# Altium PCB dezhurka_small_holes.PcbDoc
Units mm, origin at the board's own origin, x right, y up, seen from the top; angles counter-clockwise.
Board outline 60 x 25.5 mm, 2 copper layers (Top Layer, Bottom Layer); 30 components, 21 nets, 83 pads, 0 vias.
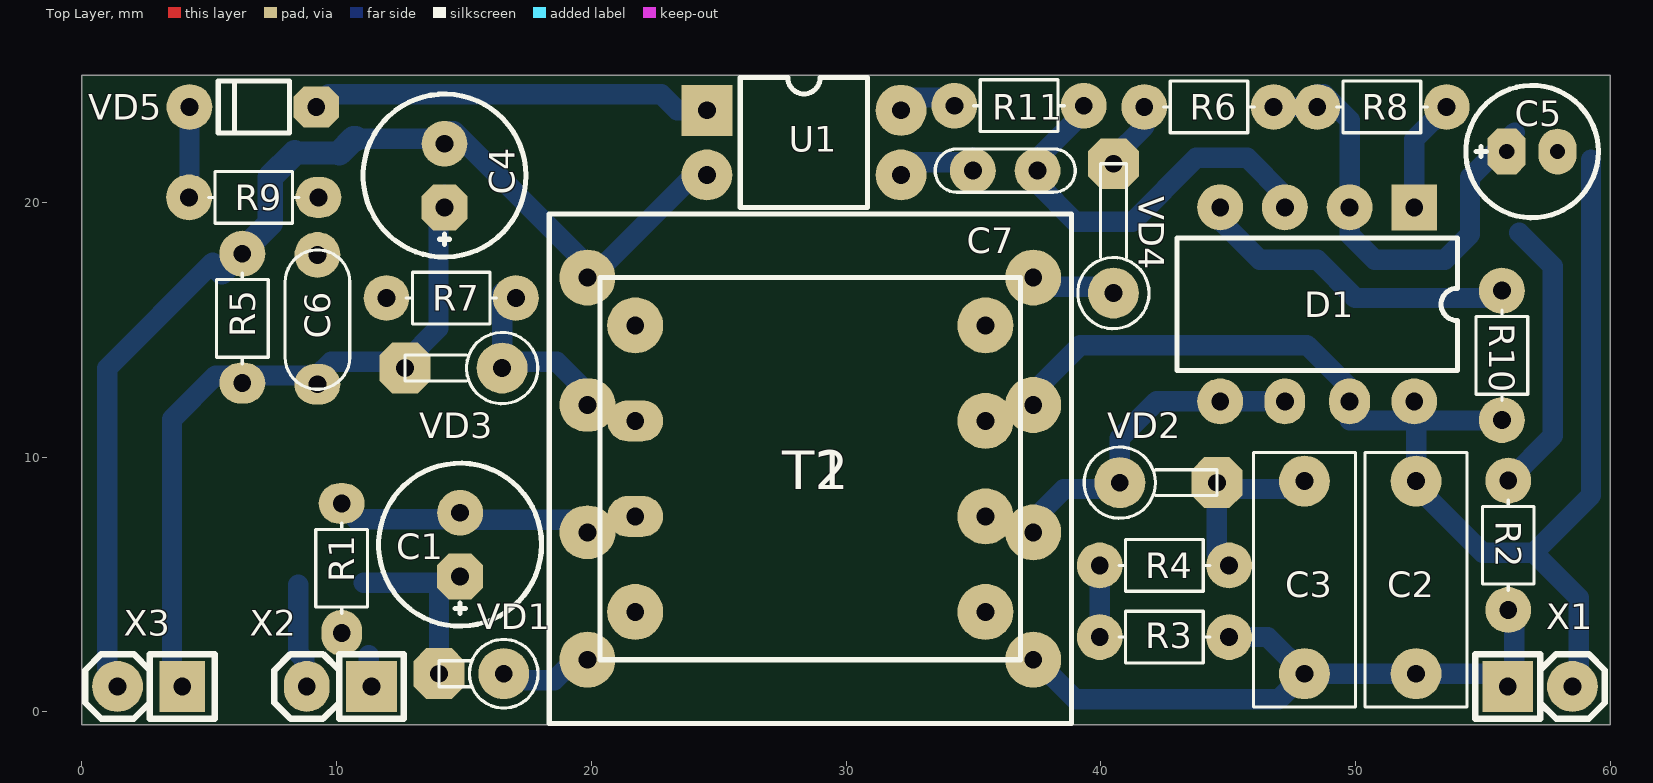
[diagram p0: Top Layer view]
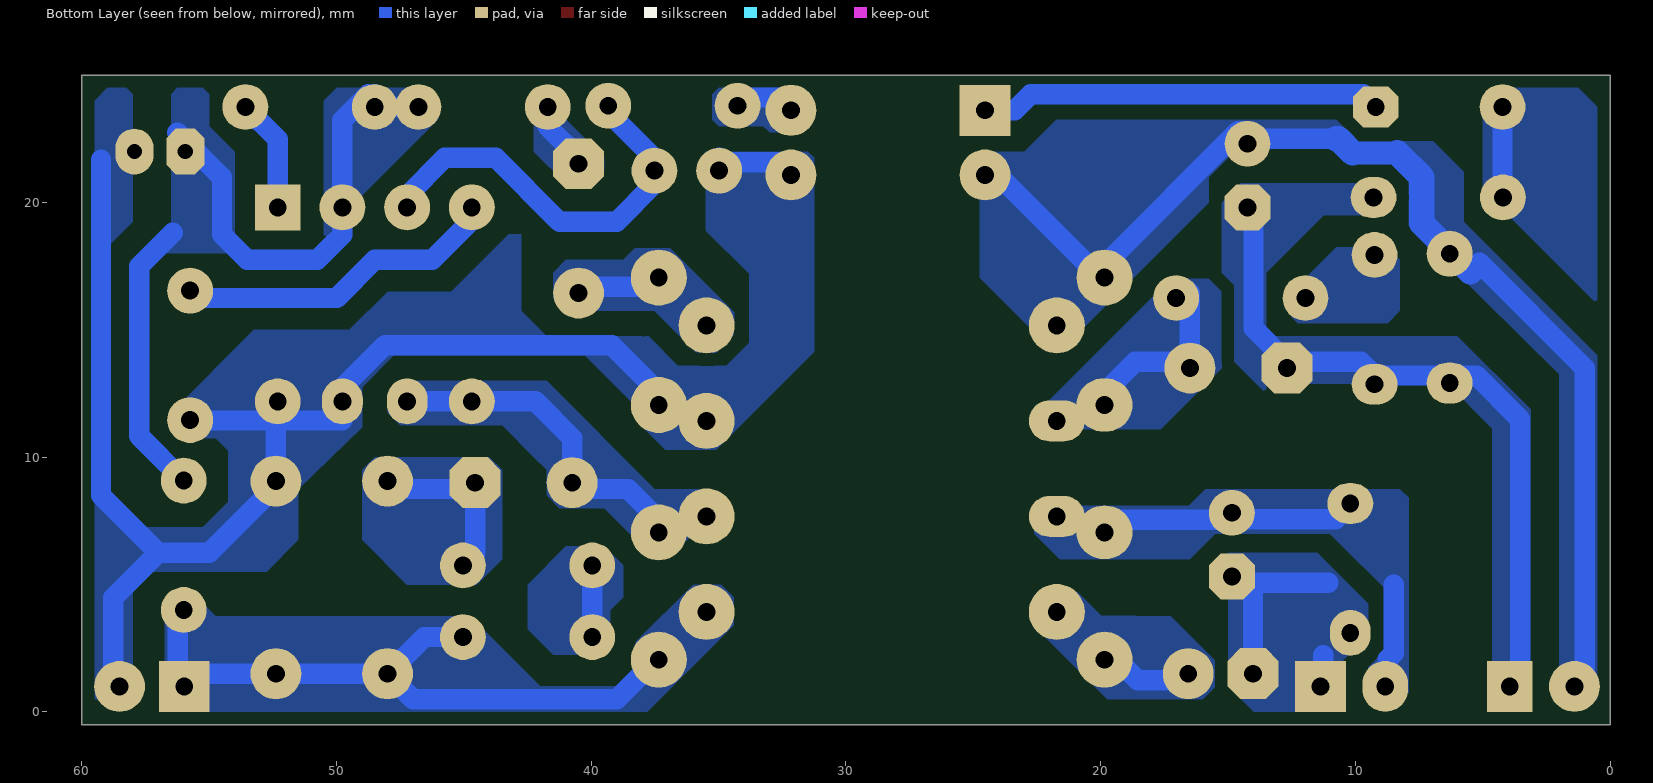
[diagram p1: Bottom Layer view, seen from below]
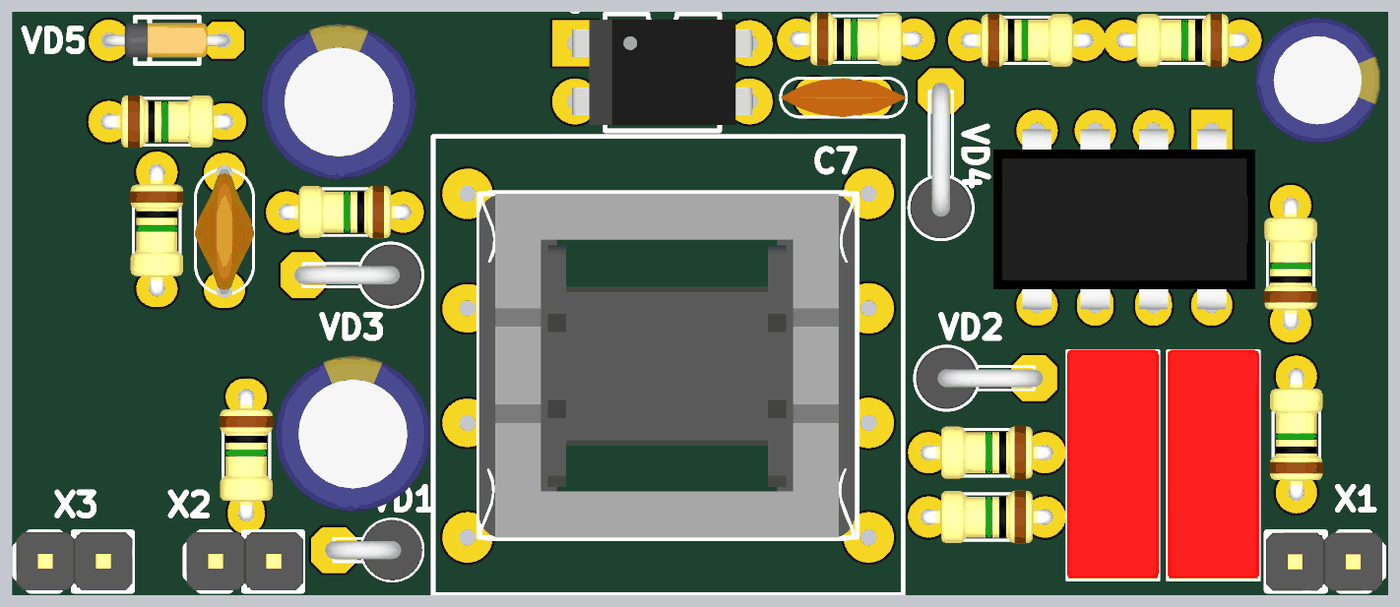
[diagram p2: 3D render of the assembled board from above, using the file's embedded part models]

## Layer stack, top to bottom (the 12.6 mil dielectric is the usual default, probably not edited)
Top Solder: solder mask 0.0102, Solder Resist, Dk 3.5
Top Layer: signal copper 0.0356
Dielectric 1: dielectric 0.32, FR-4, Dk 4.8
Bottom Layer: signal copper 0.0356
Bottom Solder: solder mask 0.0102, Solder Resist, Dk 3.5

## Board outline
0,-0.5 0,25 60,25 60,-0.5

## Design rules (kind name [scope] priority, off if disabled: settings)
Clearance [All] p1: gap=0.5 ignorepadtopadclearanceinfootprint=FALSE
PolygonConnect [All] p1: connectstyle=Direct reliefconductorwidth=0.254 reliefentries=4 polygonreliefangle="90 Angle" airgapwidth=0.254
RoomDefinition dezhurka [InComponentClass('dezhurka')] p1: confinementstyle=ConfineIn formatcopy=TRUE lockcomponents=FALSE outline 0,-0.5 60.2,-0.5 60.2,25 0,25
RoutingVias [All] p1: holewidth=0.711 width=1.27 viastyle="Through Hole" minholewidth=0.711 minwidth=1.27 maxholewidth=0.711 maxwidth=1.27
SolderMaskExpansion [All] p1: expansion=0.102
Width [All] p1: maxlimit=2 minlimit=0.3 preferedwidth=0.4
30 further rules are at their usual default settings.

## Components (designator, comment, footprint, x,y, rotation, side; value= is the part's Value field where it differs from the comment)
C1 "*" D6.3C2.5H11 14.85,6.567 r90 top
C2 "*" "MKP 10x4 h9 R7.62" 52.381,5.25 r90 top
C3 "*" "MKP 10x4 h9 R7.62" 48,5.25 r90 top
C4 "*" D6.3C2.5H11 14.237,21.057 r90 top
C5 "*" D5C2H11 56.936,22 r0 top
C6 "*" Cap-Disk-D5.5-R5.08 9.25,15.401 r270 top
C7 "*" Cap-Disk-D5.5-R2.54 36.25,21.25 r180 top
D1 "OB2358" 8-DIP 48.5,16 r270 top
R1 "*" R0.125-200#1 10.2,5.643 r270 top
R2 "*" R0.125-200#2 56,6.543 r90 top
R3 "*" R0.125-200#2 42.5,2.94 r180 top
R4 "*" R0.125-200#2 42.5,5.75 r180 top
R5 "*" R0.125-200#3 6.3,15.451 r270 top
R6 "*" R0.125-200#2 44.25,23.75 r0 top
R7 "*" R0.125-200#2 14.5,16.25 r180 top
R8 "*" R0.125-200#2 51.04,23.75 r180 top
R9 "*" R0.125-200#4 6.75,20.2 r0 top
R10 "*" R0.125-200#2 55.75,14 r90 top
R11 "*" R0.125-200#2 36.796,23.799 r0 top
T1 "3FD-312" "TRANS: EFD20_8Pin" 28.6,9.55 r90 top
T2 "3FD-312" "TRANS: EFD15_8Pin" 28.6,9.55 r90 top (schematic designator T1)
U1 "LTV-817S" 4-DIP 28.35,22.35 r0 top
VD1 "*" "DO-41 Ver-100" 16.563,1.5 r180 top
VD2 "*" "DO-41 Ver-150" 40.75,9 r0 top
VD3 "*" "DO-41 Ver-150" 16.5,13.5 r180 top
VD4 "*" "DO-41 Ver-200R" 40.5,16.443 r90 top
VD5 "*" DO35 6.75,23.75 r180 top
X1 "*" "CON: PLS-2"#1 57.25,1 r0 top
X2 "*" "CON: PLS-2"#2 10.1,1 r180 top
X3 "*" "CON: PLS-2"#3 2.67,1 r180 top

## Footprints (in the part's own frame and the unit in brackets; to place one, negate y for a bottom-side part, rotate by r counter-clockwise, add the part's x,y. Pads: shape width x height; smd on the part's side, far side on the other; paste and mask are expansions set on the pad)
4-DIP [mm]
  round 0.7 on Mech1: 0(-3.3,1.7)
  rect 2x2 hole 0.7: 1(-3.81,1.27)
  round 2 hole 0.7: 2(-3.81,-1.27) 3(3.81,-1.27) 4(3.81,1.27)
  round 0.7 on Top Overlay: 2(-3.8,2.9)
  silkscreen extent -2.5,-2.55 2.5,2.55, body extent -3.94,-2.3 3.94,2.3, height 3.66
8-DIP [mm]
  rect 1.8x1.8 hole 0.7: 1(-3.81,3.81)
  round 1.8 hole 0.7: 2(-3.81,1.27) 3(-3.81,-1.27) 4(-3.81,-3.81) 5(3.81,-3.81) 8(3.81,3.81)
  oval 1.8x1.6 hole 0.7: 6(3.81,-1.27) 7(3.81,1.27)
  round 0.5 on Mech1: ""(-3.3,5.1)
  silkscreen extent -2.6,-5.5 2.6,5.5, body extent -3.87,-5.71 4,5.71, height 4.19
Cap-Disk-D5.5-R2.54 [mm]
  round 1.8 hole 0.7: 1(-1.27,0) 2(1.27,0)
  silkscreen extent -2.75,-0.85 2.75,0.85, body extent -2.74,-0.86 2.75,0.86, height 6.25
Cap-Disk-D5.5-R5.08 [mm]
  round 1.8 hole 0.7: 1(-2.54,0)
  oval 1.6x1.8 hole 0.7: 2(2.54,0)
  silkscreen extent -2.73,-1.27 2.73,1.27, body extent -2.73,-1.27 2.73,1.27, height 7.62
"CON: PLS-2"#1 [mm]
  rect 2x2 hole 0.7: 1(-1.27,0)
  round 2 hole 0.7: 2(1.27,0)
  silkscreen extent -2.54,-1.27 2.54,1.27, body extent -2.57,-1.28 2.51,1.26, height 8.54
"CON: PLS-2"#2 [mm]
  rect 2x2 hole 0.7: 1(-1.27,0)
  oval 1.8x2 hole 0.7: 2(1.27,0)
  silkscreen extent -2.54,-1.27 2.54,1.27, body extent -2.57,-1.28 2.51,1.26, height 8.54
"CON: PLS-2"#3 [mm]
  rect 1.8x2 hole 0.7: 1(-1.27,0)
  round 2 hole 0.7: 2(1.27,0)
  silkscreen extent -2.54,-1.27 2.54,1.27, body extent -2.57,-1.28 2.51,1.26, height 8.54
D5C2H11 [mm] "Polar capacitor, diameter 5 mm, leads clearance 2 mm, height 11 mm"
  oct 1.5x1.8 hole 0.6: 1(-1,0)
  oval 1.5x1.8 hole 0.6: 2(1,0)
  silkscreen extent -2.6,-2.6 2.6,2.6, body extent -2.75,-2.75 2.75,2.75, height 13.5
D6.3C2.5H11 [mm] "Polar capacitor, diameter 6.3 mm, leads clearance 2.5 mm, height 11 mm"
  oct 1.8x1.8 hole 0.7: 1(-1.25,0)
  round 1.8 hole 0.7: 2(1.25,0)
  silkscreen extent -3.2,-3.2 3.2,3.2, body extent -3.4,-3.4 3.4,3.4, height 12.5
DO35 [mm]
  oct 1.8x1.6 hole 0.7: 1(-2.45,0)
  round 1.8 hole 0.7: 2(2.525,0)
  silkscreen extent -1.4,-1.02 1.4,1.02, body extent -2.7,-0.75 2.8,0.75, height 2.75
"DO-41 Ver-100" [mm]
  round 2 hole 0.7: 1(0,0)
  oct 2x2 hole 0.7: 2(2.54,0)
  silkscreen extent -1.35,-1.35 2.54,1.35, body extent -1.33,-1.33 2.93,1.33, height 6.84
"DO-41 Ver-150" [mm]
  round 2 hole 0.7: 1(0,0)
  oct 2x2 hole 0.7: 2(3.81,0)
  silkscreen extent -1.4,-1.4 3.81,1.4, body extent -1.33,-1.33 4.2,1.33, height 6.84
"DO-41 Ver-200R" [mm]
  round 2 hole 0.7: 1(0,0)
  oct 2x2 hole 0.7: 2(5.08,0)
  silkscreen extent -1.4,-1.4 5.08,1.4, body extent -1.33,-1.33 5.82,1.55, height 6.84
"MKP 10x4 h9 R7.62" [mm]
  round 2 hole 0.7: 1(-3.75,0) 2(3.81,0)
  silkscreen extent -5.06,-2 4.94,2, body extent -5,-2 5,2, height 9
R0.125-200#1 [mm]
  oval 1.6x1.8 hole 0.7: 1(-2.54,0)
  oval 1.8x1.6 hole 0.7: 2(2.54,0)
  silkscreen extent -1.78,-1.02 1.78,1.02, body extent -2.84,-1.15 2.84,1.15, height 2.93
R0.125-200#2 [mm]
  round 1.8 hole 0.7: 1(-2.54,0) 2(2.54,0)
  silkscreen extent -1.78,-1.02 1.78,1.02, body extent -2.84,-1.15 2.84,1.15, height 2.93
R0.125-200#3 [mm]
  round 1.8 hole 0.7: 1(-2.54,0)
  oval 1.6x1.8 hole 0.7: 2(2.54,0)
  silkscreen extent -1.78,-1.02 1.78,1.02, body extent -2.84,-1.15 2.84,1.15, height 2.93
R0.125-200#4 [mm]
  round 1.8 hole 0.7: 1(-2.54,0)
  oval 1.8x1.6 hole 0.7: 2(2.54,0)
  silkscreen extent -1.78,-1.02 1.78,1.02, body extent -2.84,-1.15 2.84,1.15, height 2.93
"TRANS: EFD15_8Pin" [mm]
  round 2.2 hole 0.7: 1(-5.625,-6.875) 2(-1.875,-6.875) 3(1.875,-6.875) 4(5.625,-6.875) 5(-5.625,6.875) 8(5.625,6.875)
  oval 1.6x2.2 hole 0.7: 6(-1.875,6.875) 7(1.875,6.875)
  silkscreen extent -7.5,-8.25 7.5,8.25, body extent -7.65,-8.18 7.65,8.25, height 8.41
"TRANS: EFD20_8Pin" [mm]
  round 2.2 hole 0.7: 1(-7.5,-8.75) 2(-2.5,-8.75) 3(2.5,-8.75) 4(7.5,-8.75) 5(-7.5,8.75) 8(7.5,8.75)
  oval 2.1x2.2 hole 0.7: 6(-2.5,8.75) 7(2.5,8.75)
  silkscreen extent -10,-10.25 10,10.25

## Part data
C1 C4 C5: library part AlumCap
C2 C3 C6 C7: library part Capacitor
D1: "Sensor", Manufacturer="Texas Instruments"
R1 R2 R3 R4 R5 R6 R7 R8 R9 R10 R11: library part Resistor
T1 T2: library part EFD20_2_OUTPUT, "Sensor", Manufacturer=Tamura
U1: library part Optoisolator, Manufacturer="Lite-On Inc."
VD1 VD2 VD3 VD4: library part Diod
VD5: library part "Diod Zener"
X1 X2 X3: library part 2-Connector

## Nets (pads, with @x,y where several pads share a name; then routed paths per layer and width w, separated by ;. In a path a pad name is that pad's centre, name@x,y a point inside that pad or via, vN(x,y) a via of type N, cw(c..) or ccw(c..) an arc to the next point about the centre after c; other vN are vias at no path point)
NetC1_1: C1.1 R1.2 VD1.2 X2.1 | length 8.7
  Bottom Layer w0.8: 11.064,5.067 14.5,5.067 14.023,4.59 VD1.2 VD1.2@14.023,1.25 ; X2.1@11.27,1 11.27,2.233
NetC1_2: C1.2 R1.1 T1.6 T2.6 X2.2 | length 13.2
  Bottom Layer w0.8: 8.5,5 8.5,3.907 8.5,2.299 8.73,2.069 X2.2@8.73,1 ; R1.1@10.766,7.567 14.5,7.567 14.517,7.55 T1.6@19.85,7.55
NetC2_1: C2.1 C3.1 R2.1 R3.1 T1.1 T2.1 X1.1 | length 27.2
  Bottom Layer w0.8: T1.1@37.35,2.55 37.35,2.15 39,0.5 47,0.5 C3.1 ; R3.1 46.56,2.94 C3.1 ; R2.1 56.23,3.773 56.23,1 55.73,1.5 C2.1 C3.1
NetC2_2: C2.2 C5.2 C7.2 D1.7 D1.8 R10.1 T1.3 T2.3 U1.3 X1.2 | length 55.4
  Bottom Layer w0.8: U1.3@32.16,21.58 34.81,21.58 34.98,21.75 C7.2 ; T1.3@37.35,12.55 39.2,14.4 48.1,14.4 49.77,12.73 D1.7 49.77,11.44 D1.8@52.31,11.44 ; R10.1 55.73,11.44 D1.8@52.31,11.44 ; X1.2@58.77,1 58.77,4.48 57,6.25 ; 59.25,21.686 59.25,8.5 57,6.25 ; D1.8@52.31,11.44 52.381,11.369 C2.2 52.381,8.56 52.69,8.56 55,6.25 57,6.25
NetC3_2: C3.2 R4.1 VD2.2 | length 6.7
  Bottom Layer w0.8: R4.1 44.56,6.23 44.56,8.75 47.81,8.75 C3.2@48,8.56
NetC4_1: C4.1 C6.2 R5.2 R9.2 VD3.2 X3.1 | length 27.8
  Bottom Layer w0.8: X3.1@3.54,1 3.54,11.5 5.25,13.21 9.25,13.21 9.79,13.75 12.69,13.75 14,15.06 14,20.07 C4.1@14.237,20.307
NetC4_2: C4.2 R5.1 T1.8 T2.8 U1.2@24.54,21.08 X3.2 | length 44.8
  Bottom Layer w0.8: X3.2@1,1 1,13.5 5.145,17.645 ; 10.75,22.5 14.237,22.5 14.237,22.807 14.593,22.807 19.85,17.55 20.51,17.55 U1.2@24.54,21.58
  Bottom Layer w0.9: 8.35,21.95 10.114,21.95
  Bottom Layer w1: 5.5,17.29 7.39,19.18 7.39,20.99 8.35,21.95 ; 10.114,21.95 10.664,22.5 10.75,22.5
NetC5_1: C5.1 D1.2 R2.2 R6.2 R8.2 | length 29.2
  Bottom Layer w0.8: R6.2@46.54,23.75 R6.2 R8.2 ; R8.2@48.75,24.25 49.77,23.23 D1.2 49.77,18.73 50.75,17.75 53.5,17.75 54.5,18.75 54.5,21 C5.1@56.25,22.75 ; R2.2 57.75,10.833 57.75,17.5 56.436,18.814
NetC6_1: C6.1 R7.2
NetC7_1: C7.1 D1.3 R11.2 | length 15.6
  Bottom Layer w0.8: C7.1@37.5,20.75 39,19.25 41.25,19.25 43.75,21.75 45.75,21.75 47.23,20.27 D1.3 ; C7.1@37.52,21.5 37.52,21.733 R11.2@39.586,23.799
NetD1_1: D1.1 R8.1 | length 4.6
  Bottom Layer w0.8: D1.1 52.31,22.48 R8.1 R8.1@53.75,23.75
NetD1_4: D1.4 R10.2 | length 12.9
  Bottom Layer w0.8: D1.4 44.69,19.31 46.25,17.75 48.5,17.75 50,16.25 55.46,16.25 R10.2
NetD1_5: D1.5 D1.6 T1.2 T2.2 VD2.1 | length 13
  Bottom Layer w0.8: T1.2@37.35,7.55 38.55,8.75 40.75,8.75 VD2.1 40.75,10.75 42.19,12.19 D1.5 D1.6
NetR3_2: R3.2 R4.2 | length 2.6
  Bottom Layer w0.8: R3.2@39.96,3.19 R4.2
NetR6_1: R6.1 VD4.2 | length 2.5
  Bottom Layer w0.8: VD4.2@40.5,21.773 41.71,22.983 R6.1
NetR7_1: R7.1 T1.7 T2.7 VD3.1 | length 6.6
  Bottom Layer w0.8: R7.1@16.5,16.46 16.5,13.75 18.65,13.75 T1.7@19.85,12.55
NetR9_1: R9.1 VD5.2 | length 3.3
  Bottom Layer w0.8: R9.1@4.21,20.5 4.225,20.515 VD5.2
NetR11_1: R11.1 U1.4 | length 1.9
  Bottom Layer w0.8: U1.4@32.41,24.12 R11.1@34.327,24.12
NetT1_4: T1.4 T2.4 VD4.1 | length 3.5
  Bottom Layer w0.8: T1.4@37.35,17.55 38.207,16.693 VD4.1@40.5,16.693
NetT1_5: T1.5 T2.5 VD1.1 | length 3.8
  Bottom Layer w0.8: VD1.1@16.563,1.25 18.55,1.25 T1.5@19.85,2.55
NetU1_1: U1.1 VD5.1 | length 15.8
  Bottom Layer w0.8: VD5.1 9.7,24.25 22.75,24.25 23.38,23.62 U1.1
pads on no net: D1. U1.0 U1.2@24.55,25.25

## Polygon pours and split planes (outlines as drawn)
NetC2_2 on Bottom Layer "NETC2_2_L02_P024" (solid, pour order 24): 37.75,14.75 36.6,13.6 34.7,13.6 33.8,14.5 33.8,17.2 35.5,18.9 35.5,22 31.5,22 31.25,21.75 31.25,14.15 35.1,10.3 37.1,10.3 37.9,11.1 38,14.75
NetC4_1 on Bottom Layer "NETC4_1_L02_P040" (solid, pour order 40): 15.25,20 15.25,17.25 14.75,16.75 14.75,13.75 13.5,12.5 13.5,17.25 11.25,19.5 9.75,19.5 9.75,20.75 10,20.75 14.5,20.75
NetC5_1 on Bottom Layer "NETC5_1_L02_P012" (solid, pour order 12): 57.75,18 56.5,19.25 56.5,24.25 56.25,24.5 55.25,24.5 55,24.25 55,23 54,22 54,18
NetC2_1 on Bottom Layer "NETC2_1_L02_P000" (solid, pour order 0): 36,5 38.25,2.75 38.25,1.75 39,1 42,1 43.75,2.75 44.75,3.75 54.75,3.75 55.5,4.5 56.25,4.5 56.75,4 56.75,0 37.8,0 34.4,3.4 34.4,4.5 34.9,5
NetR3_2 on Bottom Layer "NETR3_2_L02_P002" (solid, pour order 2): 39.25,2.625 39.25,4 38.75,4.5 38.75,5.75 39.5,6.5 41,6.5 42.5,5 42.5,3.25 41.5,2.25 39.75,2.25
NetC3_2 on Bottom Layer "NETC3_2_L02_P004" (solid, pour order 4): 43.5,6 44.5,5 47.25,5 49,6.75 49,9.5 48.5,10 44,10 43.5,9.5
NetC2_2 on Bottom Layer "NETC2_2_L02_P008" (solid, pour order 8): 58,0.5 58,4.75 57.25,5.5 52.75,5.5 51.5,6.75 51.5,8.75 49,11.184 49,12.75 47.75,14 40.25,14 38,11.75 37,11.75 37,13.75 38,14.75 41.75,14.75 42.75,15.75 42.75,18.75 43.25,18.75 45.5,16.5 48,16.5 49.5,15 53.25,15 56.5,11.75 56.5,11.25 56,10.75 54.75,10.75 54.25,10.25 54.25,8.25 55.25,7.25 59,7.25 59.5,6.75 59.5,0.5
NetC2_2 on Bottom Layer "NETC2_2_L02_P010" (solid, pour order 10): 59.504,6.019 59.5,24 59,24.5 58.25,24.5 58,24.25 58,19.25 59,18.25 59,8.75 56.5,6.25
NetC5_1 on Bottom Layer "NETC5_1_L02_P014" (solid, pour order 14): 50.5,18.5 50.5,24 50,24.5 46.5,24.5 46,24 46,23.27 49.77,19.5
NetT1_4 on Bottom Layer "NETT1_4_L02_P016" (solid, pour order 16): 38.3,18.2 38.75,17.75 41,17.75 41.5,17.25 41.5,16.25 41,15.75 37.524,15.75 35.9,14.126 35.1,14.1 34.4,14.8 34.383,15.683 36.9,18.2
NetD1_5 on Bottom Layer "NETD1_5_L02_P018" (solid, pour order 18): 47.5,13 41.75,13 37.5,8.75 35.475,8.75 35.475,7.525 36.75,6.25 37.75,6.25 39.5,8 41.25,8 41.75,8.5 41.75,9.5 42.25,10 43.5,11.25 47.5,11.25 48,11.75 48,12.5
NetR6_1 on Bottom Layer "NETR6_1_L02_P020" (solid, pour order 20): 41,20.75 42.25,22 42.25,23.75 41.875,24.125 39.5,21.75 39.5,21.25 40,20.75
NetR11_1 on Bottom Layer "NETR11_1_L02_P022" (solid, pour order 22): 31.75,24.5 31.25,24 31.25,23.25 31.5,23.25 32,22.75 33,22.75 33.25,23 35,23 35.25,23.25 35.25,24.25 35,24.5
NetC1_2 on Bottom Layer "NETC1_2_L02_P026" (solid, pour order 26): 7.9,0.75 7.9,8.4 8.25,8.75 11.75,8.75 12.25,8.75 15.9,8.75 16.55,8.1 22.6,8.1 22.6,7 21.6,6 16.5,6 15.5,7 11,7 8.5,4.5 8.5,2.75 9.5,1.75 9.5,0.75
NetT1_5 on Bottom Layer "NETT1_5_L02_P028" (solid, pour order 28): 20.925,4.725 20,3.8 17.25,3.75 15.5,2 15.5,1 16,0.5 19.75,0.5 22.45,3.2
NetC1_1 on Bottom Layer "NETC1_1_L02_P030" (solid, pour order 30): 15,1 15,4.5 15.5,5 15.5,5.75 15,6.25 11.5,6.25 9.5,4.25 9.5,3 10.5,2 10.5,0 14,0
NetC4_1 on Bottom Layer "NETC4_1_L02_P032" (solid, pour order 32): 13.625,12.875 6.375,12.875 4.625,11.125 4.625,0.375 3.125,0.375 3.125,11.875 6,14.75 14,14.75 14.5,14.25 14.5,13.75
NetR7_1 on Bottom Layer "NETR7_1_L02_P034" (solid, pour order 34): 22.375,11.875 17.25,17 15.75,17 15.25,16.5 15.25,13.5 17.65,11.1 21.6,11.1
NetC4_2 on Bottom Layer "NETC4_2_L02_P036" (solid, pour order 36): 8.3,22.4 7.9,20.8 7.9,19.092 2,13.25 2,0.75 1.75,0.5 0.5,0.5 0.5,0.75 0.5,1 0.5,14 5.75,19.25 5.75,21.211 6.939,22.4
NetC4_2 on Bottom Layer "NETC4_2_L02_P042" (solid, pour order 42): 20.65,15.1 15.75,20 15.75,21 14.5,22.25 10,22.25 10,22.5 10.75,23.25 21.75,23.25 23,22 24.75,22 24.75,17.05 22.8,15.1
NetC6_1 on Bottom Layer "NETC6_1_L02_P044" (solid, pour order 44): 12.5,16.5 10.75,18.25 8.75,18.25 8.25,17.75 8.25,15.75 8.75,15.25 12.25,15.25 12.5,15.5
NetR9_1 on Bottom Layer "NETR9_1_L02_P038" (solid, pour order 38): 5,23.475 5,20.5 0.5,16 0.5,23.75 1.25,24.5 3.975,24.5

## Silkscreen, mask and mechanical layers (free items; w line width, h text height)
Border:
  the board outline again, w0.2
